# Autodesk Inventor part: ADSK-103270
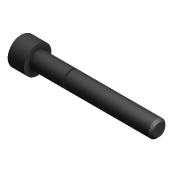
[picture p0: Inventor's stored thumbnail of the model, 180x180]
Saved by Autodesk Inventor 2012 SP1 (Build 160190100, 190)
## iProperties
Created: 2000-09
Part Number: ADSK-103270
Description: Hexagon Socket Head Cap Screw
Document SubType Name: Modeling
Standard: ANSI B18.3 - No. 10 - 24 - 1 3/8
Density: 1 g/cm^3
Material: Default
Control State: 0
Master: False
Checked Out: False
Shininess: 0.0
Density: 0.0
Volumn: 0.0
Area: 0.0
PropertySet Name: Model Information
Author: Administrator
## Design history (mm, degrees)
node "Base1"
body "Solid1"
